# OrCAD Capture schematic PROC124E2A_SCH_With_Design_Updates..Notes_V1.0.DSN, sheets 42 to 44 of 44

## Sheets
42 41. OSCILLATOR: size C; title: OSCILLATOR
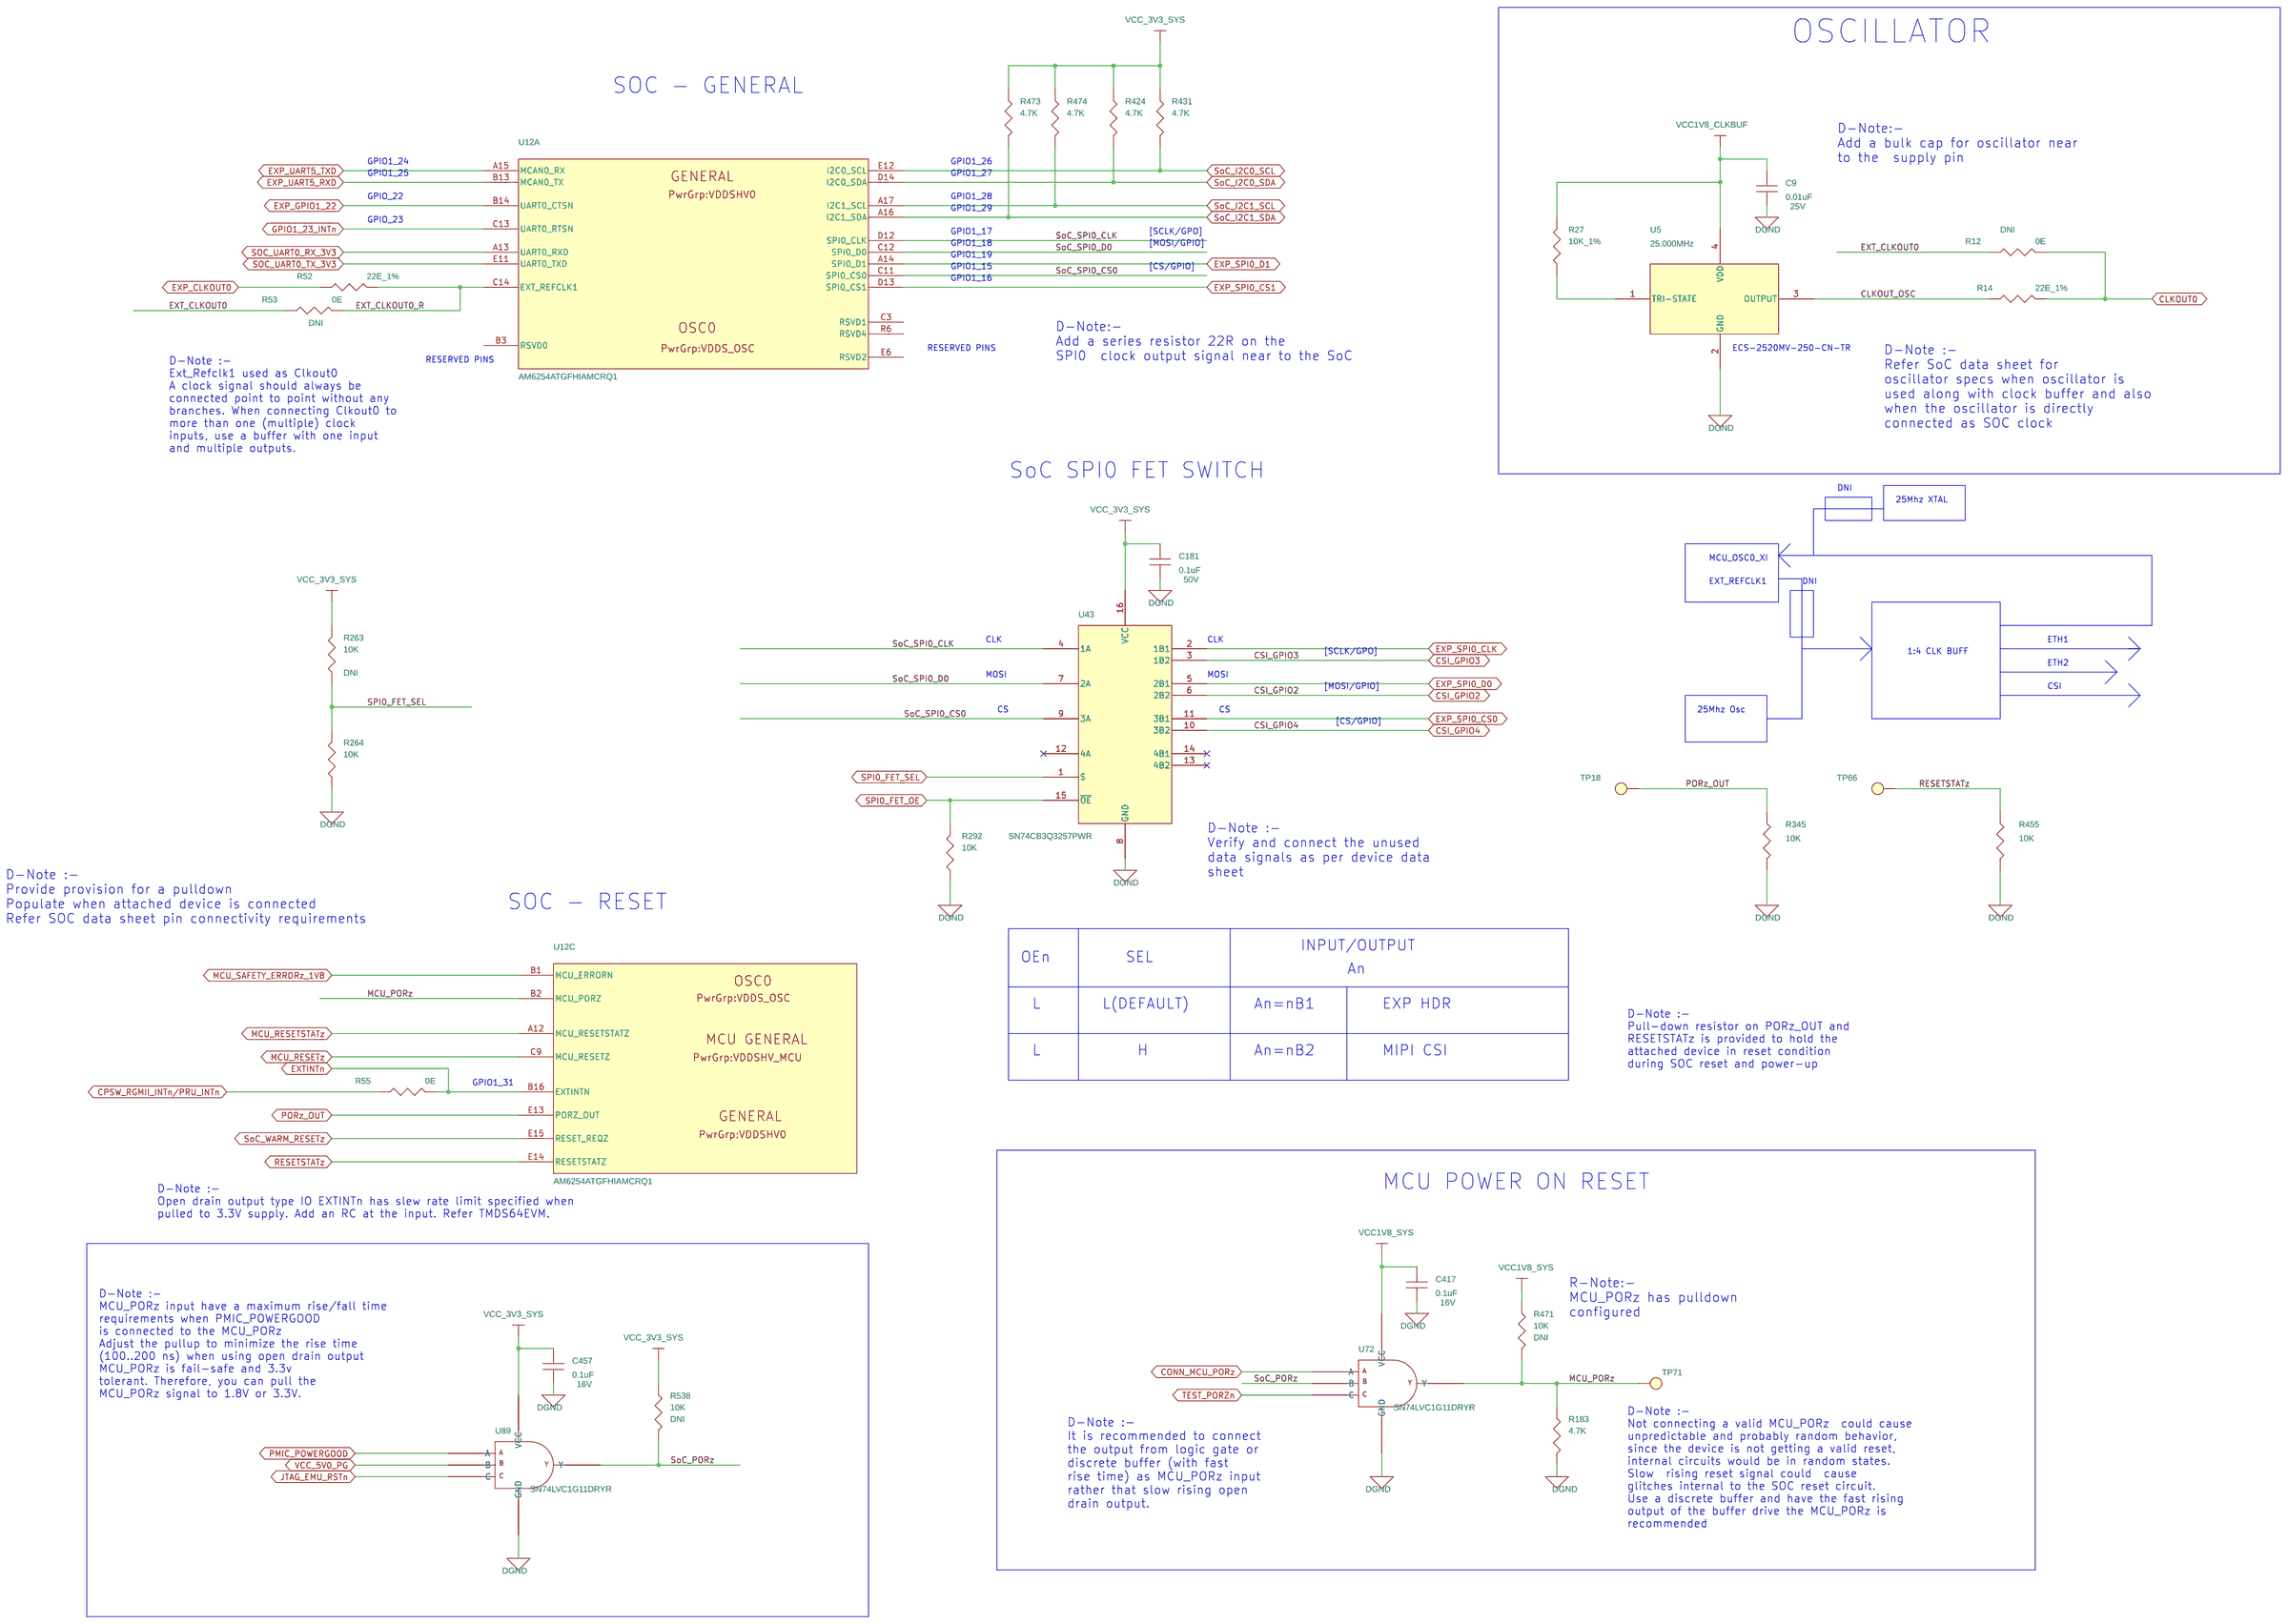
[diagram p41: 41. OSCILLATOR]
43 42. RESET: size C; title: RESET
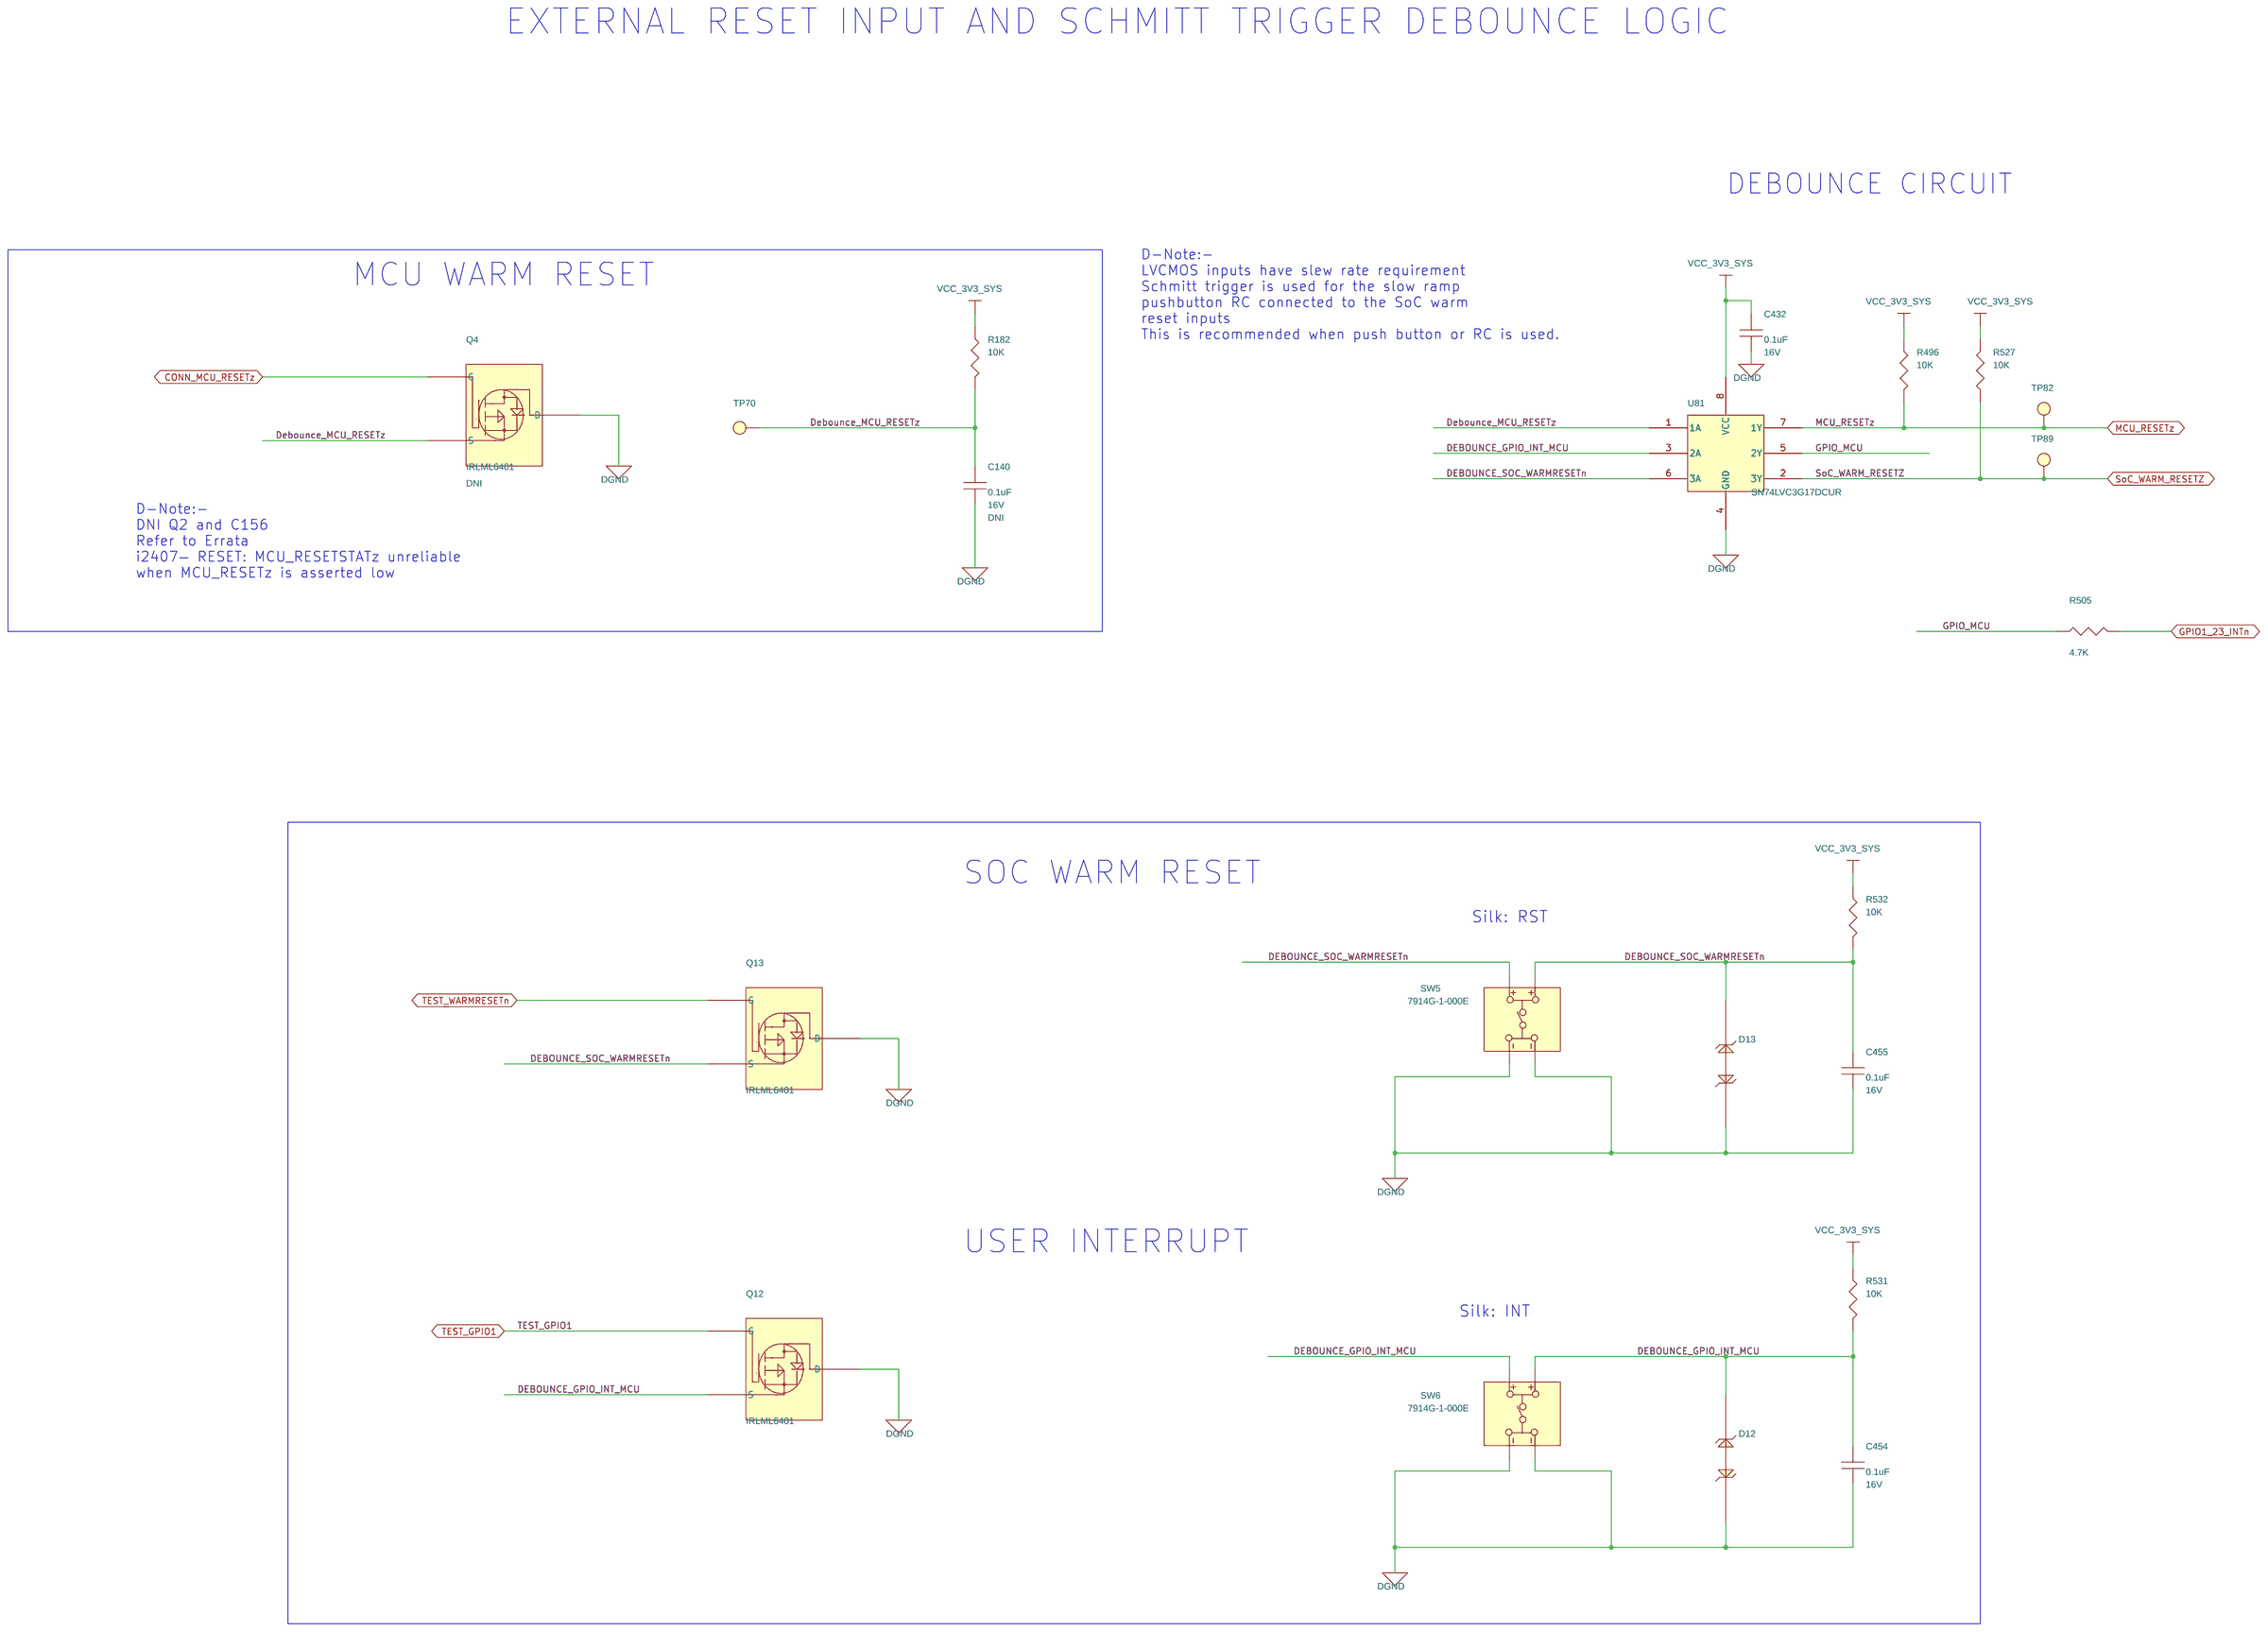
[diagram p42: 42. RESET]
44 44. ACCESSORIES: title: HARDWARE SCHEMATICS
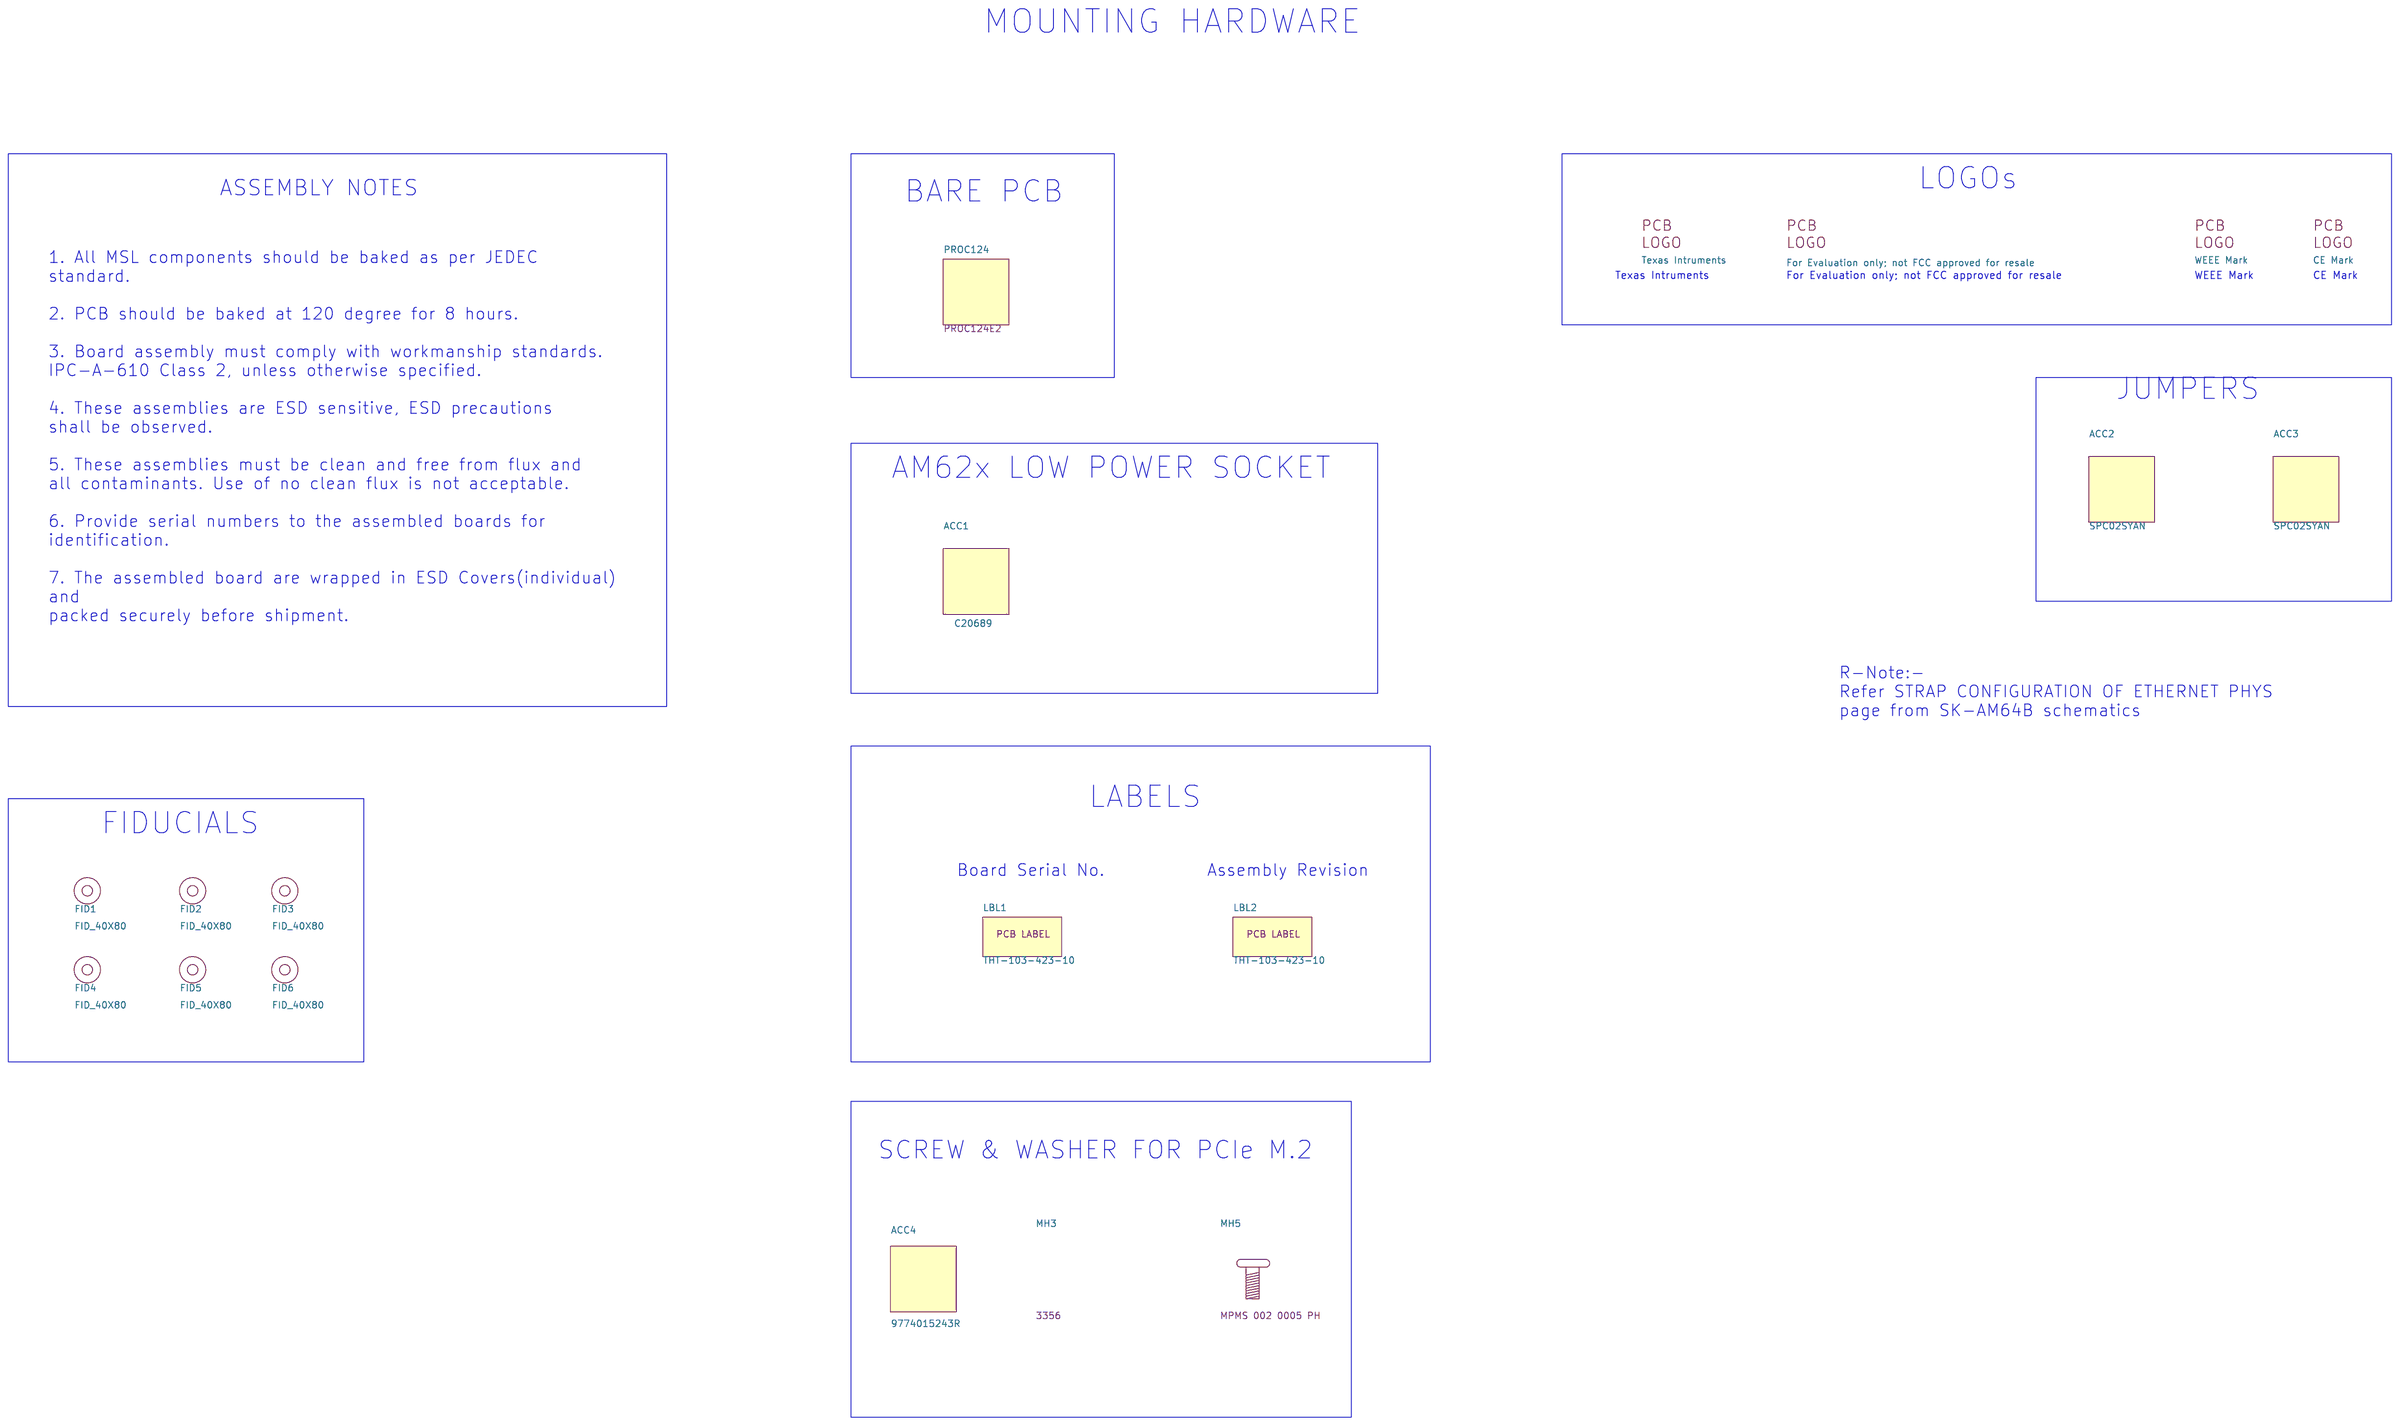
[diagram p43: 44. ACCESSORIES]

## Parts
sheet 15. SOC POWER CAPS
U12  AM6254ATGFHIAMCRQ1  [FCBGA441_31-49_680X680_2-6]  (sections A,B,C,D,E,F,G,H,I,J,K,L,M,N,O,P,Q,R)
sheet 41. OSCILLATOR
C9  0.01uF  [CAP0201_0-5]
C181  0.1uF  [CAP0402_0-75]
C417  0.1uF  [CAP0201_0-5]
C457  0.1uF  [CAP0201_0-5]
R12  0E  [RES0201_0-5]
R14  22E_1%  [RES0201_0-5]
R27  10K_1%  [RES0201_0-5]
R52  22E_1%  [RES0201_0-5]
R53  0E  [RES0201_0-5]
R55  0E  [RES0201_0-5]
R183  4.7K  [RES0201_0-5]
R263  10K  [RES0201_0-5]
R264  10K  [RES0201_0-5]
R292  10K  [RES0201_0-5]
R345  10K  [RES0201_0-5]
R424  4.7K  [RES0201_0-5]
R431  4.7K  [RES0201_0-5]
R455  10K  [RES0201_0-5]
R471  10K  [RES0201_0-5]
R473  4.7K  [RES0201_0-5]
R474  4.7K  [RES0201_0-5]
R538  10K  [RES0201_0-5]
TP18  TP20_SMD  [TP20_SMD]
TP66  TP20_SMD  [TP20_SMD]
TP71  TP20_SMD  [TP20_SMD]
U5  25.000MHz  [OSC4_ECS-2520MV_100X80_SMD_0-9]
U43  SN74CB3Q3257PWR  [TSSOP16_25-59_205X180]
U72  SN74LVC1G11DRYR  [SON6_SN74LVC2G17_40X60_0-6]
U89  SN74LVC1G11DRYR  [SON6_SN74LVC2G17_40X60_0-6]
sheet 42. RESET
C140  0.1uF  [CAP0201_0-5]
C432  0.1uF  [CAP0201_0-5]
C454  0.1uF  [CAP0201_0-5]
C455  0.1uF  [CAP0201_0-5]
D12  TPD1E10B06DPYR  [DIO_DFN0402_0-5]
D13  TPD1E10B06DPYR  [DIO_DFN0402_0-5]
Q4  IRLML6401  [TO_SOT23-123]
Q12  IRLML6401  [TO_SOT23-123]
Q13  IRLML6401  [TO_SOT23-123]
R182  10K  [RES0201_0-5]
R496  10K  [RES0201_0-5]
R505  4.7K  [RES0201_0-5]
R527  10K  [RES0201_0-5]
R531  10K  [RES0201_0-5]
R532  10K  [RES0201_0-5]
SW5  7914G-1-000E  [SW4_100X216_200X200_SMD_4-2]
SW6  7914G-1-000E  [SW4_100X216_200X200_SMD_4-2]
TP70  TP20_SMD  [TP20_SMD]
TP82  TP20_SMD  [TP20_SMD]
TP89  TP20_SMD  [TP20_SMD]
U81  SN74LVC3G17DCUR  [VSSOP8_19-68_85X95_0-9]
sheet 44. ACCESSORIES
ACC1  C20689  [BGASKT435_C20689_880X880_11]
ACC2  SPC02SYAN  [NA]
ACC3  SPC02SYAN  [NA]
ACC4  9774015243R  [NA]
FID1  FID_40X80  [FID_40X80]
FID2  FID_40X80  [FID_40X80]
FID3  FID_40X80  [FID_40X80]
FID4  FID_40X80  [FID_40X80]
FID5  FID_40X80  [FID_40X80]
FID6  FID_40X80  [FID_40X80]
LBL1  THT-103-423-10  [NA]
LBL2  THT-103-423-10  [NA]
LOGO1  Texas Intruments  [TI_Stacked_Overlay_Small]
LOGO2  For Evaluation only; not FCC approved for resale  [FCC_disclaimer]
LOGO3  WEEE Mark  [TI_Stacked_Overlay_Small]
LOGO4  CE Mark  [TI_Stacked_Overlay_Small]
MH3  FLAT WASHER_M2  [NA]
MH5  PAN HEAD_M2 X 5  [NA]
PCB1  PROC124

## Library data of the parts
U12 = AM6254ATGFHIAMCRQ1_FCBGA441: IC AM62Q SoC MICROPROCESSOR FCBGA441; Chkd/date: PRADEEP/180324; Crtd /date: TAMILARASU/180324; Custom_Duty: 15%; Customs_HS_Code: 85423100; Distributor_name: NA; Distributor_part_number: NA; Footprint Path: Y:\MIS_DATABASE\Library\ALTIUM_TOOL\PCB_FOOTPRINTS\Altium_Footprint_Lib.PcbLib; Height: 2.57MM; Library Path: Y:\MIS_DATABASE\Library\ALTIUM_TOOL\SCHEMATICS_PARTS\MS_MICROPROCESSOR_Library.schlib; Mfr_name: TEXAS INSTRUMENTS; Mistral Part No: 141224030001-R; Package: FCBGA441; Part_type: ICS\DIGITAL\MICROPROCESSOR; Project: TI_AM62Q_BRD; RoHS: NA; Temperature: NA; Tolerance: NA; Voltage: NA; Wattage: NA; Weight: NA; Datasheet: Y:\MIS_DATABASE\DATASHEETS\ICS\DIGITAL\MICROCONTROLLER\AM62Q-SoC.PDF
C9 = CAP: CAP CERAMIC 0.01uF 25V 10% X5R 0201; Chkd/date: MANIRAJA/230118; Crtd /date: MANIRAJA/230118; Custom_Duty: 15%; Customs_HS_Code: 85322990; Distributor_name: DIGIKEY; Distributor_part_number: GRM033R61E103KA12J-ND; Footprint Path: Y:\MIS_DATABASE\Library\ALTIUM_TOOL\PCB_FOOTPRINTS\Altium_Footprint_Lib.PcbLib; Height: 0.33MM; Library Path: Y:\MIS_DATABASE\Library\ALTIUM_TOOL\SCHEMATICS_PARTS\MS_DISCRETE_Library.schlib; Mfr_name: MURATA; Mfr_part_number: GRM033R61E103KA12J; Mistral Part No: 120018010007-R; Package: 0201; Part_type: CAPACITORS\CERAMIC; Project: TI_MAXIE_CPB; RoHS: RoHS; Temperature: -55°C+85°C; Tolerance: 10%; Voltage: 25V; Wattage: NA; Weight: 0.33mg; Datasheet: Y:\MIS_DATABASE\DATASHEETS\CAPACITORS\GRM033R61E103KA12.PDF
C181 = CAP: CAP CERAMIC 0.1uF 50V 10% X7R 0402; Alt_Mfr_name: YAGEO AMERICA; Alt_Mfr_part_number: CC0402KRX5R8BB104; Chkd/date: MANIRAJA/261020; Crtd /date: ALVY/211020; Custom_Duty: 15%; Customs_HS_Code: 85322990; Distributor_name: DIGIKEY; Distributor_part_number: 490-10700-1-ND; Footprint Path: Y:\MIS_DATABASE\Library\ALTIUM_TOOL\PCB_FOOTPRINTS\Altium_Footprint_Lib.PcbLib; Height: 0.55MM; Library Path: Y:\MIS_DATABASE\Library\ALTIUM_TOOL\SCHEMATICS_PARTS\MS_DISCRETE_Library.schlib; Mfr_name: MURATA; Mfr_part_number: GRM155R71H104KE14D; Mistral Part No: 120011100014-R; Package: 0402; Part_type: CAPACITORS\CERAMIC; Project: J7_CP; RoHS: RoHS; Temperature: -55°C+125°C; Tolerance: 10%; Voltage: 50V; Wattage: NA; Weight: 3.1mg; Datasheet: Y:\MIS_DATABASE\DATASHEETS\CAPACITORS\GRM155R71H104KE14.PDF
C417 C432 C454 C455 C457 = CAP: CAP CERAMIC 0.1uF 16V 10% X5R 0201; Alt_Mfr_name: YAGEO AMERICA; Alt_Mfr_part_number: CC0402KRX5R8BB104; Chkd/date: MANIRAJA/230118; Crtd /date: MANIRAJA/230118; Custom_Duty: 15%; Customs_HS_Code: 85322990; Distributor_name: DIGIKEY; Distributor_part_number: 490-14305-1-ND; Footprint Path: Y:\MIS_DATABASE\Library\ALTIUM_TOOL\PCB_FOOTPRINTS\Altium_Footprint_Lib.PcbLib; Height: 0.33MM; Library Path: Y:\MIS_DATABASE\Library\ALTIUM_TOOL\SCHEMATICS_PARTS\MS_DISCRETE_Library.schlib; Mfr_name: MURATA; Mfr_part_number: GRM033R61C104KE14D; Mistral Part No: 120009030072-R; Package: 0201; Part_type: CAPACITORS\CERAMIC; Project: TI_MAXIE_CPB; RoHS: RoHS; Temperature: -55°C+85°C; Tolerance: 10%; Voltage: 16V; Wattage: NA; Weight: 0.33mg; Datasheet: Y:\MIS_DATABASE\DATASHEETS\CAPACITORS\GRM033R61C104KE14.PDF
R12 R53 = RESISTOR: RES 0E 1/20W 5% 0201; Assembly_Instruction: DNI; Chkd/date: NAVEED/301214; Crtd /date: MUDDU/120710; Custom_Duty: 15%; Customs_HS_Code: 85332119; Distributor_name: DIGIKEY; Distributor_part_number: 311-0.0NCT-ND; Footprint Path: Y:\MIS_DATABASE\Library\ALTIUM_TOOL\PCB_FOOTPRINTS\Altium_Footprint_Lib.PcbLib; Height: 0.26MM; Library Path: Y:\MIS_DATABASE\Library\ALTIUM_TOOL\SCHEMATICS_PARTS\MS_DISCRETE_Library.schlib; Mfr_name: YAGEO AMERICA; Mfr_part_number: RC0201JR-070RL; Mistral Part No: 110010070067-R; Package: 0201; Part_type: RESISTORS\FIXED; Project: PB_BUGBASE; RoHS: RoHS; Temperature: -55°C+125°C; Tolerance: 5%; Voltage: NA; Wattage: 1/20W; Weight: 0.17mg; Datasheet: Y:\MIS_DATABASE\DATASHEETS\RESISTORS\RCXXXXL-SER_MAR18.PDF
R14 R52 = RESISTOR: RES 22E 1/20W 1% 0201; Chkd/date: PRAVEEN/080922; Crtd /date: TAMILARASU/080922; Custom_Duty: 15%; Customs_HS_Code: 85332119; Distributor_name: DIGIKEY; Distributor_part_number: P122843CT-ND; Footprint Path: Y:\MIS_DATABASE\Library\ALTIUM_TOOL\PCB_FOOTPRINTS\Altium_Footprint_Lib.PcbLib; Height: 0.26MM; Library Path: Y:\MIS_DATABASE\Library\ALTIUM_TOOL\SCHEMATICS_PARTS\MS_DISCRETE_Library.schlib; Mfr_name: PANASONIC-ECG; Mfr_part_number: ERJ-1GNF22R0C; Mistral Part No: 110022090007-R; Package: 0201; Part_type: RESISTORS\FIXED; Project: SK AM62Q LP EVM BRD; RoHS: RoHS; Temperature: -55°C+125°C; Tolerance: 1%; Voltage: NA; Wattage: 1/20W; Weight: 0.15mg; Datasheet: Y:\MIS_DATABASE\DATASHEETS\RESISTORS\PAN-ERJSER_NOV17.PDF
R27 = RESISTOR: RES 10K 1/20W 1% 0201; Chkd/date: VASANTHA/270117; Crtd /date: MANIRAJA/270117; Custom_Duty: 15%; Customs_HS_Code: 85332119; Distributor_name: DIGIKEY; Distributor_part_number: 311-10.0KMCT-ND; Footprint Path: Y:\MIS_DATABASE\Library\ALTIUM_TOOL\PCB_FOOTPRINTS\Altium_Footprint_Lib.PcbLib; Height: 0.26MM; Library Path: Y:\MIS_DATABASE\Library\ALTIUM_TOOL\SCHEMATICS_PARTS\MS_DISCRETE_Library.schlib; Mfr_name: YAGEO AMERICA; Mfr_part_number: RC0201FR-0710KL; Mistral Part No: 110011040018-R; Package: 0201; Part_type: RESISTORS\FIXED; Project: GOLDEN-I LITE; RoHS: RoHS; Temperature: -55°C+125°C; Tolerance: 1%; Voltage: NA; Wattage: 1/20W; Weight: 0.17mg; Datasheet: Y:\MIS_DATABASE\DATASHEETS\RESISTORS\RCXXXXL-SER_MAR18.PDF
R55 = RESISTOR: RES 0E 1/20W 5% 0201; Chkd/date: NAVEED/301214; Crtd /date: MUDDU/120710; Custom_Duty: 15%; Customs_HS_Code: 85332119; Distributor_name: DIGIKEY; Distributor_part_number: 311-0.0NCT-ND; Footprint Path: Y:\MIS_DATABASE\Library\ALTIUM_TOOL\PCB_FOOTPRINTS\Altium_Footprint_Lib.PcbLib; Height: 0.26MM; Library Path: Y:\MIS_DATABASE\Library\ALTIUM_TOOL\SCHEMATICS_PARTS\MS_DISCRETE_Library.schlib; Mfr_name: YAGEO AMERICA; Mfr_part_number: RC0201JR-070RL; Mistral Part No: 110010070067-R; Package: 0201; Part_type: RESISTORS\FIXED; Project: PB_BUGBASE; RoHS: RoHS; Temperature: -55°C+125°C; Tolerance: 5%; Voltage: NA; Wattage: 1/20W; Weight: 0.17mg; Datasheet: Y:\MIS_DATABASE\DATASHEETS\RESISTORS\RCXXXXL-SER_MAR18.PDF
R183 R424 R431 R473 R474 = RESISTOR: RES 4.7K 1/20W 5% 0201; Chkd/date: MANIRAJA/200921; Crtd /date: ALVY/200921; Custom_Duty: 15%; Customs_HS_Code: 85332119; Distributor_name: DIGIKEY; Distributor_part_number: 311-4.7KNCT-ND; Footprint Path: Y:\MIS_DATABASE\Library\ALTIUM_TOOL\PCB_FOOTPRINTS\Altium_Footprint_Lib.PcbLib; Height: 0.26MM; Library Path: Y:\MIS_DATABASE\Library\ALTIUM_TOOL\SCHEMATICS_PARTS\MS_DISCRETE_Library.schlib; Mfr_name: YAGEO AMERICA; Mfr_part_number: RC0201JR-074K7L; Mistral Part No: 110021090007-R; Package: 0201; Part_type: RESISTORS\FIXED; Project: TI_AM62x SKEVM_BRD; RoHS: RoHS; Temperature: -55°C+125°C; Tolerance: 5%; Voltage: NA; Wattage: 1/20W; Weight: 0.17mg; Datasheet: Y:\MIS_DATABASE\DATASHEETS\RESISTORS\RCXXXXL-SER_MAR18.PDF
R263 R471 R538 = RESISTOR: RES 10K 1/20W 5% 0201; Assembly_Instruction: DNI; Chkd/date: MANIRAJA/050517; Crtd /date: MANIRAJA/050517; Custom_Duty: 15%; Customs_HS_Code: 85332119; Distributor_name: DIGIKEY; Distributor_part_number: 311-10KNCT-ND; Footprint Path: Y:\MIS_DATABASE\Library\ALTIUM_TOOL\PCB_FOOTPRINTS\Altium_Footprint_Lib.PcbLib; Height: 0.26MM; Library Path: Y:\MIS_DATABASE\Library\ALTIUM_TOOL\SCHEMATICS_PARTS\MS_DISCRETE_Library.schlib; Mfr_name: YAGEO AMERICA; Mfr_part_number: RC0201JR-0710KL; Mistral Part No: 110010070051-R; Package: 0201; Part_type: RESISTORS\FIXED; Project: GOLDEN-I LITE; RoHS: RoHS; Temperature: -55°C+125°C; Tolerance: 5%; Voltage: NA; Wattage: 1/20W; Weight: 0.17mg; Datasheet: Y:\MIS_DATABASE\DATASHEETS\RESISTORS\RCXXXXL-SER_MAR18.PDF
R182 R264 R292 R345 R455 R496 R527 R531 R532 = RESISTOR: RES 10K 1/20W 5% 0201; Chkd/date: MANIRAJA/050517; Crtd /date: MANIRAJA/050517; Custom_Duty: 15%; Customs_HS_Code: 85332119; Distributor_name: DIGIKEY; Distributor_part_number: 311-10KNCT-ND; Footprint Path: Y:\MIS_DATABASE\Library\ALTIUM_TOOL\PCB_FOOTPRINTS\Altium_Footprint_Lib.PcbLib; Height: 0.26MM; Library Path: Y:\MIS_DATABASE\Library\ALTIUM_TOOL\SCHEMATICS_PARTS\MS_DISCRETE_Library.schlib; Mfr_name: YAGEO AMERICA; Mfr_part_number: RC0201JR-0710KL; Mistral Part No: 110010070051-R; Package: 0201; Part_type: RESISTORS\FIXED; Project: GOLDEN-I LITE; RoHS: RoHS; Temperature: -55°C+125°C; Tolerance: 5%; Voltage: NA; Wattage: 1/20W; Weight: 0.17mg; Datasheet: Y:\MIS_DATABASE\DATASHEETS\RESISTORS\RCXXXXL-SER_MAR18.PDF
TP18 TP66 TP70 TP71 TP82 TP89 = TESTPOINT: TESTPOINT CIR 20 SMD; Chkd/date: SHREESHAIL/171006; Crtd /date: MAZHAR/171006; Custom_Duty: NA; Customs_HS_Code: NA; Distributor_name: NA; Distributor_part_number: NA; Footprint Path: Y:\MIS_DATABASE\Library\ALTIUM_TOOL\PCB_FOOTPRINTS\Altium_Footprint_Lib.PcbLib; Height: NA; Library Path: Y:\MIS_DATABASE\Library\ALTIUM_TOOL\SCHEMATICS_PARTS\MS_DISCRETE_Library.schlib; MECHANICAL 3D STEP FILE: NA; Mfr_name: LOCAL; Mistral Part No: NA; Package: SMD; Project: BT MODULE_CSRBC04; RoHS: NA; Temperature: NA; Tolerance: NA; Voltage: NA; Wattage: NA; Weight: NA; Datasheet: NA
U5 = OSC4_ASFL3: OSC 25.000MHz CMOS SMD; Chkd/date: MANIRAJA/181120; Crtd /date: ALVY/181120; Custom_Duty: 24%; Customs_HS_Code: 85437099; Distributor_name: DIGIKEY; Distributor_part_number: XC2752CT-ND; Footprint Path: Y:\MIS_DATABASE\Library\ALTIUM_TOOL\PCB_FOOTPRINTS\Altium_Footprint_Lib.PcbLib; Height: 0.90MM; Library Path: Y:\MIS_DATABASE\Library\ALTIUM_TOOL\SCHEMATICS_PARTS\MS_DISCRETE_Library.schlib; Mfr_name: ECS INC; Mfr_part_number: ECS-2520MV-250-CN-TR; Mistral Part No: 130020110041-R; Package: SMD; Part_type: OSCILLATORS; Project: AM64X_SKEVM; RoHS: RoHS; Temperature: -40°C+85°C; Tolerance: NA; Voltage: NA; Wattage: NA; Weight: 311mg; Datasheet: Y:\MIS_DATABASE\DATASHEETS\MISC\CRY_OSC\ECS-2520MV.PDF
U43 = SN74CB3Q3257PWR_TSSOP16: IC 4BIT 1-OF-2 FET MULTIPLEXER/DEMULTIPLEXER TSSOP16; Chkd/date: SUHAS/251010; Crtd /date: USMAN/060109; Custom_Duty: 15%; Customs_HS_Code: 85423100; Distributor_name: DIGIKEY; Distributor_part_number: 296-19138-1-ND; Footprint Path: Y:\MIS_DATABASE\Library\ALTIUM_TOOL\PCB_FOOTPRINTS\Altium_Footprint_Lib.PcbLib; Footprint Ref: TSSOP16_25-59_205X180_1-2; Height: 1.20MM; Library Path: Y:\MIS_DATABASE\Library\ALTIUM_TOOL\SCHEMATICS_PARTS\MS_COMBINATIONAL_Library.schlib; MECHANICAL 3D STEP FILE: TSSOP16_25-59_205X180_1-2; Mfr_name: TEXAS INSTRUMENTS; Mistral Part No: 141009030117-R; Package: TSSOP16; Part_type: ICS\DIGITAL\COMBINATIONAL; Project: OMAP_EVM; RoHS: Sb/ Br FREE; Temperature: -40°C+85°C; Datasheet: Y:\MIS_DATABASE\DATASHEETS\ICS\DIGITAL\COMBINATIONAL\SN74CB3Q3257.PDF
U72 U89 = SN74LVC1G11DCKR_SC70-6: IC SINGLE 3-INPUT POSITIVE-AND GATE SON6; Chkd/date: MANIRAJA/270121; Crtd /date: ALVY/270121; Custom_Duty: 15%; Customs_HS_Code: 85423100; Distributor_name: DIGIKEY; Distributor_part_number: 296-30120-1-ND; Footprint Path: Y:\MIS_DATABASE\Library\ALTIUM_TOOL\PCB_FOOTPRINTS\Altium_Footprint_Lib.PcbLib; Height: 0.60MM; Library Path: Y:\MIS_DATABASE\Library\ALTIUM_TOOL\SCHEMATICS_PARTS\MS_GATE_Library.schlib; Mfr_name: TEXAS INSTRUMENTS; Mistral Part No: 141021010013-R; Package: SON6; Part_type: ICS\DIGITAL\GATES; Project: AM64X_SKEVM; RoHS: RoHS; Temperature: -40°C+125°C; Tolerance: NA; Voltage: NA; Wattage: NA; Weight: 33mg; Datasheet: Y:\MIS_DATABASE\DATASHEETS\ICS\DIGITAL\GATES\SN74LVC1G_NOV16.PDF
C140 = CAP: CAP CERAMIC 0.1uF 16V 10% X5R 0201; Alt_Mfr_name: YAGEO AMERICA; Alt_Mfr_part_number: CC0402KRX5R8BB104; Assembly_Instruction: DNI; Chkd/date: MANIRAJA/230118; Crtd /date: MANIRAJA/230118; Custom_Duty: 15%; Customs_HS_Code: 85322990; Distributor_name: DIGIKEY; Distributor_part_number: 490-14305-1-ND; Footprint Path: Y:\MIS_DATABASE\Library\ALTIUM_TOOL\PCB_FOOTPRINTS\Altium_Footprint_Lib.PcbLib; Height: 0.33MM; Library Path: Y:\MIS_DATABASE\Library\ALTIUM_TOOL\SCHEMATICS_PARTS\MS_DISCRETE_Library.schlib; Mfr_name: MURATA; Mfr_part_number: GRM033R61C104KE14D; Mistral Part No: 120009030072-R; Package: 0201; Part_type: CAPACITORS\CERAMIC; Project: TI_MAXIE_CPB; RoHS: RoHS; Temperature: -55°C+85°C; Tolerance: 10%; Voltage: 16V; Wattage: NA; Weight: 0.33mg; Datasheet: Y:\MIS_DATABASE\DATASHEETS\CAPACITORS\GRM033R61C104KE14.PDF
D12 D13 = DIODE_SOD323: DIODE 1CH ESD PROTECTION X1SON2; Chkd/date: MANIRAJA/040420; Crtd /date: VASANTHA/181114; Custom_Duty: 15%; Customs_HS_Code: 85423100; Distributor_name: DIGIKEY; Distributor_part_number: 296-30406-1-ND; Footprint Path: Y:\MIS_DATABASE\Library\ALTIUM_TOOL\PCB_FOOTPRINTS\Altium_Footprint_Lib.PcbLib; Height: 0.45MM; Library Path: Y:\MIS_DATABASE\Library\ALTIUM_TOOL\SCHEMATICS_PARTS\MS_DISCRETE_Library.schlib; Mfr_name: TEXAS INSTRUMENTS; Mistral Part No: 130014110022-R; Package: X1SON2; Part_type: DIODE; Project: GALILEO_EVM; RoHS: RoHS; Temperature: -40°C+125°C; Tolerance: NA; Voltage: NA; Wattage: NA; Weight: 1mg; Datasheet: Y:\MIS_DATABASE\DATASHEETS\ICS\INTERFACE\TPD1E10B06-SER.PDF
Q4 = MOSFET_IRLML6401TR: TRANSISTOR MOSFET P-CHANNEL SOT23-3; Assembly_Instruction: DNI; Chkd/date: SHREESHAIL/020206; Crtd /date: MAZHAR/040505; Custom_Duty: 15%; Customs_HS_Code: 85412900; Distributor_name: DIGIKEY; Distributor_part_number: IRLML6401PBFCT-ND; Height: 1.11MM; Mfr_name: IRF; Mfr_part_number: IRLML6401TRPBF; Mistral Part No: 130009031213-P; Package: SOT23-3; Part_type: TRANSISTOR\MOSFET; Project: G4_SVGA; RoHS: Pb-Free; Temperature: -55°C+150°C; Tolerance: NA; Voltage: NA; Wattage: NA; Weight: NA; Datasheet: Y:\MIS_DATABASE\DATASHEETS\DISCRETES\TRANSISTORS_FETS\IRLML6401.PDF
Q12 Q13 = MOSFET_IRLML6401TR: TRANSISTOR MOSFET P-CHANNEL SOT23-3; Chkd/date: SHREESHAIL/020206; Crtd /date: MAZHAR/040505; Custom_Duty: 15%; Customs_HS_Code: 85412900; Distributor_name: DIGIKEY; Distributor_part_number: IRLML6401PBFCT-ND; Height: 1.11MM; Mfr_name: IRF; Mfr_part_number: IRLML6401TRPBF; Mistral Part No: 130009031213-P; Package: SOT23-3; Part_type: TRANSISTOR\MOSFET; Project: G4_SVGA; RoHS: Pb-Free; Temperature: -55°C+150°C; Tolerance: NA; Voltage: NA; Wattage: NA; Weight: NA; Datasheet: Y:\MIS_DATABASE\DATASHEETS\DISCRETES\TRANSISTORS_FETS\IRLML6401.PDF
R505 = RESISTOR: RES 4.7K 1/20W 5% 0201; Chkd/date: MANIRAJA/200921; Crtd /date: ALVY/200921; Custom_Duty: 15%; Customs_HS_Code: 85332119; Distributor_name: DIGIKEY; Distributor_part_number: 311-4.7KNCT-ND; Footprint Path: Y:\MIS_DATABASE\Library\ALTIUM_TOOL\PCB_FOOTPRINTS\Altium_Footprint_Lib.PcbLib; Height: 0.26MM; Library Path: Y:\MIS_DATABASE\Library\ALTIUM_TOOL\SCHEMATICS_PARTS\MS_DISCRETE_Library.schlib; Manufacturer: YAGEO AMERICA; Mfr_name: YAGEO AMERICA; Mfr_part_number: RC0201JR-074K7L; Mistral Part No: 110021090007-R; Package: 0201; Part_type: RESISTORS\FIXED; Project: TI_AM62x SKEVM_BRD; RoHS: RoHS; Temperature: -55°C+125°C; Tolerance: 5%; Voltage: NA; Wattage: 1/20W; Weight: 0.17mg; Datasheet: Y:\MIS_DATABASE\DATASHEETS\RESISTORS\RCXXXXL-SER_MAR18.PDF
SW5 SW6 = 7914G-1-000E__7914G: SWITCH SPST-NO 4MM SQ SMD 7914G; Chkd/date: VASANTHA/271216; Crtd /date: BAVISH/051010; Custom_Duty: 24%; Customs_HS_Code: 85369090; Distributor_name: DIGIKEY; Distributor_part_number: 7914G-000ECT-ND; Height: 4.19MM; Library Ref: 7914G-1-000E _7914G; Mfr_name: BOURNS; Mistral Part No: 130015110004-R; Package: 7914G; Part_type: ELECTRO-MECHANICAL\SWITCH; Project: AAAUC; RoHS: RoHS; Temperature: -55°C+125°C; Tolerance: NA; Voltage: NA; Wattage: NA; Weight: NA; Datasheet: Y:\MIS_DATABASE\DATASHEETS\ICS\DIGITAL\COMBINATIONAL\7914G-1-000E.PDF
U81 = SN74LVC3G17DCUR_VSSOP8: IC TRIPLE SCHMITT-TRIGGER BUFFER VSSOP8; Chkd/date: MANIRAJA/280917; Crtd /date: MANIRAJA/280917; Custom_Duty: 15%; Customs_HS_Code: 85423100; Distributor_name: DIGIKEY; Distributor_part_number: 296-18818-1-ND; Height: 0.90MM; Mfr_name: TEXAS INSTRUMENTS; Mistral Part No: 141017090019-R; Package: VSSOP8; Part_type: ICS\DIGITAL\COMBINATIONAL; Project: TI_MAXIE_CPB; RoHS: RoHS; Temperature: -40°C+125°C; Tolerance: NA; Voltage: NA; Wattage: NA; Weight: 9.6mg; Datasheet: Y:\MIS_DATABASE\DATASHEETS\ICS\DIGITAL\COMBINATIONAL\SN74LVC3G17.PDF
ACC1 = ACCESSORY: ACCESSORIE BGA SOCKET J7VCL MICROPROCESSOR BGA435; Chkd/date: ALVY/161220; Crtd /date: MANIRAJA/161220; Custom_Duty: NA; Customs_HS_Code: NA; Distributor_name: NA; Distributor_part_number: NA; Footprint Path: NA; Height: 10.93MM; Library Path: NA; Mfr_name: IRONWOOD ELECTRONICS; Mistral Part No: 160020120073; Package: BGA435; Part_type: ACCESSORIES; Project: J7VCL_EVM; RoHS: NA; Temperature: -55°C+160°C; Tolerance: NA; Voltage: NA; Wattage: NA; Weight: 19620mg; Datasheet: Y:\MIS_DATABASE\DATASHEETS\MISC\ACCESSORIES\C20689.PDF
ACC2 ACC3 = ACCESSORY: ACCESSORIE JUMPER SHORTING GOLD FLASH; Chkd/date: SUHAS\211010; Crtd /date: USMAN/301208; Distributor_name: DIGIKEY; Distributor_part_number: S9001-ND; Footprint Path: Y:\MIS_DATABASE\Library\ALTIUM_TOOL\PCB_FOOTPRINTS\Altium_Footprint_Lib.PcbLib; Library Path: Y:\MIS_DATABASE\Library\ALTIUM_TOOL\SCHEMATICS_PARTS\MS_MECHANICAL_Library.schlib; Mfr_name: SULLINS CONNECTOR; Mistral Part No: 160009030153-R; Part_type: ACCESSORIES; Project: SMART VIEW_NVR; RoHS: RoHS; Temperature: -55°C+105°C; Datasheet: Y:\MIS_DATABASE\DATASHEETS\MISC\MODULES\SPC02SYAN.PDF
ACC4 = ACCESSORY: STANDOFF BOARD TO BOARD 1.50MM LENGTH FEMALE M2 THREADED SS; Chkd/date: MANIRAJA/280219; Crtd /date: ALVY/280219; Distributor_name: DIGIKEY; Distributor_part_number: 732-7069-1-ND; Mfr_name: WURTH ELECTRONICS; Mistral Part No: 160019020049-R; Package: SS; Part_type: MECHANICAL\STANDOFF; Project: TI_J7ES_EVM_CP; RoHS: RoHS; Weight: 178mg; Datasheet: Y:\MIS_DATABASE\DATASHEETS\MISC\MECHANICAL\9774015243R.PDF
FID1-FID6 = Fiducial
LBL1 LBL2 = ACCESSORY_THT-3-423-10: ACCESSORIE 1 WORKHORSE POLYSTER LABLE 0.25" X 1"; Chkd/date: MANIRAJA/270218; Crtd /date: ALVY/260218; Footprint Path: Y:\MIS_DATABASE\Library\ALTIUM_TOOL\PCB_FOOTPRINTS\Altium_Footprint_Lib.PcbLib; Library Path: Y:\MIS_DATABASE\Library\ALTIUM_TOOL\SCHEMATICS_PARTS\MS_MECHANICAL_Library.schlib; Mfr_name: BRADY; Mistral Part No: 160018020185; Part_type: ACCESSORIES; Project: TI_MAXIE_CPB
LOGO1 LOGO3 LOGO4 = TI_Logo
LOGO2 = FCC_disclaimer
MH3 = WASHER_FLAT: FLAT WASHER FOR M2 NYLON; Chkd/date: MANIRAJA/110319; Crtd /date: ALVY/110319; Distributor_name: DIGIKEY; Distributor_part_number: 36-3356-ND; Mfr_name: KEYSTONE; Mfr_part_number: 3356; Mistral Part No: 160019030017-R; Package: NYLON; Part_type: MECHANICAL\WASHERS; Project: TI_J7ES_EVM_CP; RoHS: RoHS; Datasheet: Y:\MIS_DATABASE\DATASHEETS\MISC\MECHANICAL\3356.PDF
MH5 = SCREW_PAN: PHILLIPS PAN HEAD SCREW - M2 X 5; Chkd/date: MANIRAJA/150319; Crtd /date: MANIRAJA/150319; Distributor_name: DIGIKEY; Distributor_part_number: H738-ND; Height: 5.00MM; Mfr_name: B AND F FASTENER; Mfr_part_number: MPMS 002 0005 PH; Mistral Part No: 160019030026-R; Part_type: MECHANICAL\SCREWS; Project: TI_J7ES_EVM_CP; RoHS: RoHS; Datasheet: Y:\MIS_DATABASE\DATASHEETS\MISC\MECHANICAL\SCREW_MPMSXXX.PDF
PCB1 = PCB_0: AM62x LOW POWER SKEVM; Mfr_part_number: PROC124E2

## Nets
DGND: C9.1 C140.1 C181.1 C417.1 C432.1 C454.1 C455.1 C457.1 D12.1 D13.1 Q4.3(D) Q12.3(D) Q13.3(D) R183.2 R264.1 R292.1 R345.2 R455.2 SW5.1 SW5.4 SW6.1 SW6.4 U5.2(GND) U43.8(GND) U72.2(GND) U81.4(GND) U89.2(GND) ; also on sheet 1 2 3 4 13 14 15 16 17 18 19 20 21 22 23 24 25 26 27 28 29 30 31 32 33 34 35 36 37 38 39 40 41
VCC1V8_CLKBUF: C9.2 R27.2 U5.4(VDD) ; also on sheet 25
VCC1V8_SYS: C417.2 R471.1 U72.5(VCC) ; also on sheet 4 16 19 20 22 25 34 37 39 40
VCC_3V3_SYS: C181.2 C432.2 C457.2 R182.1 R263.2 R424.1 R431.1 R473.1 R474.1 R496.1 R527.2 R531.1 R532.1 R538.1 U43.16(VCC) U81.8(VCC) U89.5(VCC) ; also on sheet 1 4 15 16 19 20 21 23 24 26 27 29 30 31 32 33 34 36 37 38 39 40 41
VCC_5V0_PG: U89.3(B) ; also on sheet 14
CLKOUT0: R12.2 R14.2 ; also on sheet 25
CLKOUT_OSC: R14.1 U5.3(OUTPUT)
CONN_MCU_PORz: U72.1(A) ; also on sheet 34
CONN_MCU_RESETz: Q4.1(G) ; also on sheet 34
CPSW_RGMII_INTn/PRU_INTn: R55.1 ; also on sheet 24 32
CSI_GPIO2: U43.6(2B2) ; also on sheet 38
CSI_GPIO3: U43.3(1B2) ; also on sheet 38
CSI_GPIO4: U43.10(3B2) ; also on sheet 38
DEBOUNCE_GPIO_INT_MCU: C454.2 D12.2 Q12.2(S) R531.2 SW6.2 SW6.3 U81.3(2A)
Debounce_MCU_RESETz: C140.2 Q4.2(S) R182.2 TP70.1(TP) U81.1(1A)
DEBOUNCE_SOC_WARMRESETn: C455.2 D13.2 Q13.2(S) R532.2 SW5.2 SW5.3 U81.6(3A)
EXP_CLKOUT0: R52.1 ; also on sheet 33
EXP_GPIO1_22: U12.B14(UART0_CTSN) ; also on sheet 33
EXP_SPI0_CLK: U43.2(1B1) ; also on sheet 33
EXP_SPI0_CS0: U43.11(3B1) ; also on sheet 33
EXP_SPI0_CS1: U12.D13(SPI0_CS1) ; also on sheet 33
EXP_SPI0_D0: U43.5(2B1) ; also on sheet 33
EXP_SPI0_D1: U12.A14(SPI0_D1) ; also on sheet 33
EXP_UART5_RXD: U12.B13(MCAN0_TX) ; also on sheet 33
EXP_UART5_TXD: U12.A15(MCAN0_RX) ; also on sheet 33
EXT_CLKOUT0: R12.1 R53.1
EXT_CLKOUT0_R: R52.2 R53.2 U12.C14(EXT_REFCLK1)
EXTINTn: R55.2 U12.B16(EXTINTN) ; also on sheet 4
GPIO1_23_INTn: R505.2 U12.C13(UART0_RTSN) ; also on sheet 39
GPIO_MCU: R505.1 U81.5(2Y)
JTAG_EMU_RSTn: U89.6(C) ; also on sheet 30
MCU_PORz: R183.1 R471.2 TP71.1(TP) U12.B2(MCU_PORZ) U72.4(Y)
MCU_RESETSTATz: U12.A12(MCU_RESETSTATZ) ; also on sheet 32 34
MCU_RESETz: R496.2 TP82.1(TP) U12.C9(MCU_RESETZ) U81.7(1Y)
MCU_SAFETY_ERRORz_1V8: U12.B1(MCU_ERRORN) ; also on sheet 34
PMIC_POWERGOOD: U89.1(A) ; also on sheet 4
PORz_OUT: R345.1 TP18.1(TP) U12.E13(PORZ_OUT) ; also on sheet 1 21 24 27
RESETSTATz: R455.1 TP66.1(TP) U12.E14(RESETSTATZ) ; also on sheet 1 4 20 21 22 24 27 32 37 38 39 40 41
SoC_I2C0_SCL: R431.2 U12.E12(I2C0_SCL) ; also on sheet 4 13 23 32 33 37
SoC_I2C0_SDA: R424.2 U12.D14(I2C0_SDA) ; also on sheet 4 13 23 32 33 37
SOC_I2C1_SCL: R474.2 U12.A17(I2C1_SCL) ; also on sheet 16 23 26 39 40 41
SOC_I2C1_SDA: R473.2 U12.A16(I2C1_SDA) ; also on sheet 16 23 26 39 40 41
SoC_PORz: R538.2 U72.3(B) U89.4(Y)
SoC_SPI0_CLK: U12.D12(SPI0_CLK) U43.4(1A)
SoC_SPI0_CS0: U12.C11(SPI0_CS0) U43.9(3A)
SoC_SPI0_D0: U12.C12(SPI0_D0) U43.7(2A)
SOC_UART0_RX_3V3: U12.A13(UART0_RXD) ; also on sheet 31
SOC_UART0_TX_3V3: U12.E11(UART0_TXD) ; also on sheet 31
SoC_WARM_RESETZ: R527.1 TP89.1(TP) U12.E15(RESET_REQZ) U81.2(3Y)
SPI0_FET_OE: R292.2 U43.15(~{OE}) ; also on sheet 39
SPI0_FET_SEL: R263.1 R264.2 U43.1(S) ; also on sheet 39
TEST_GPIO1: Q12.1(G) ; also on sheet 26 28
TEST_PORZn: U72.6(C) ; also on sheet 26 28
TEST_WARMRESETn: Q13.1(G) ; also on sheet 26 28
N16947096: R27.1 U5.1(TRI-STATE)

Not connected (* = marked no-connect by the designer): U12 B3(RSVD0) C3(RSVD1) E6(RSVD2) R6(RSVD4); U43 12(4A)* 13(4B2)* 14(4B1)*

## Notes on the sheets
sheet 42
- OSCILLATOR
- SOC - GENERAL
- D-Note:-
  Add a bulk cap for oscillator near
  to the  supply pin
- GPIO1_24
- GPIO1_26
- GPIO1_25
- GPIO1_27
- GPIO_22
- GPIO1_28
- GPIO1_29
- GPIO_23
- GPIO1_17
- [SCLK/GPO]
- GPIO1_18
- [MOSI/GPIO]
- GPIO1_19
- GPIO1_15
- [CS/GPIO]
- GPIO1_16
- D-Note:-
  Add a series resistor 22R on the
  SPI0  clock output signal near to the SoC
- D-Note :-
  Ext_Refclk1 used as Clkout0
  A clock signal should always be
  connected point to point without any
  branches. When connecting Clkout0 to
  more than one (multiple) clock
  inputs, use a buffer with one input
  and multiple outputs.
- RESERVED PINS
- RESERVED PINS
- ECS-2520MV-250-CN-TR
- D-Note :-
  Refer SoC data sheet for
  oscillator specs when oscillator is
  used along with clock buffer and also
  when the oscillator is directly
  connected as SOC clock
- SoC SPI0 FET SWITCH
- DNI
- 25Mhz XTAL
- MCU_OSC0_XI
- EXT_REFCLK1
- DNI
- CLK
- CLK
- ETH1
- [SCLK/GPO]
- 1:4 CLK BUFF
- ETH2
- MOSI
- MOSI
- [MOSI/GPIO]
- CSI
- CS
- CS
- 25Mhz Osc
- [CS/GPIO]
- D-Note :-
  Verify and connect the unused
  data signals as per device data
  sheet
- D-Note :-
  Provide provision for a pulldown
  Populate when attached device is connected
  Refer SOC data sheet pin connectivity requirements
- SOC - RESET
- INPUT/OUTPUT
- OEn
- SEL
- An
- L
- L(DEFAULT)
- An=nB1
- EXP HDR
- D-Note :-
  Pull-down resistor on PORz_OUT and
  RESETSTATz is provided to hold the
  attached device in reset condition
  during SOC reset and power-up
- L
- H
- An=nB2
- MIPI CSI
- GPIO1_31
- MCU POWER ON RESET
- D-Note :-
  Open drain output type IO EXTINTn has slew rate limit specified when
  pulled to 3.3V supply. Add an RC at the input. Refer TMDS64EVM.
- R-Note:-
  MCU_PORz has pulldown
  configured
- D-Note :-
  MCU_PORz input have a maximum rise/fall time
  requirements when PMIC_POWERGOOD
  is connected to the MCU_PORz
  Adjust the pullup to minimize the rise time
  (100..200 ns) when using open drain output
  MCU_PORz is fail-safe and 3.3v
  tolerant. Therefore, you can pull the
  MCU_PORz signal to 1.8V or 3.3V.
- D-Note :-
  Not connecting a valid MCU_PORz  could cause
  unpredictable and probably random behavior,
  since the device is not getting a valid reset,
  internal circuits would be in random states.
  Slow  rising reset signal could  cause
  glitches internal to the SOC reset circuit.
  Use a discrete buffer and have the fast rising
  output of the buffer drive the MCU_PORz is
  recommended
- D-Note :-
  It is recommended to connect
  the output from logic gate or
  discrete buffer (with fast
  rise time) as MCU_PORz input
  rather that slow rising open
  drain output.
sheet 43
- EXTERNAL RESET INPUT AND SCHMITT TRIGGER DEBOUNCE LOGIC
- DEBOUNCE CIRCUIT
- D-Note:-
  LVCMOS inputs have slew rate requirement
  Schmitt trigger is used for the slow ramp
  pushbutton RC connected to the SoC warm
  reset inputs
  This is recommended when push button or RC is used.
- MCU WARM RESET
- D-Note:-
  DNI Q2 and C156
  Refer to Errata
  i2407— RESET: MCU_RESETSTATz unreliable
  when MCU_RESETz is asserted low
- SOC WARM RESET
- Silk: RST
- USER INTERRUPT
- Silk: INT
sheet 44
- MOUNTING HARDWARE
- LOGOs
- ASSEMBLY NOTES
- BARE PCB
- 1. All MSL components should be baked as per JEDEC
  standard.
  2. PCB should be baked at 120 degree for 8 hours.
  3. Board assembly must comply with workmanship standards.
  IPC-A-610 Class 2, unless otherwise specified.
  4. These assemblies are ESD sensitive, ESD precautions
  shall be observed.
  5. These assemblies must be clean and free from flux and
  all contaminants. Use of no clean flux is not acceptable.
  6. Provide serial numbers to the assembled boards for
  identification.
  7. The assembled board are wrapped in ESD Covers(individual)
  and
  packed securely before shipment.
- Texas Intruments
- For Evaluation only; not FCC approved for resale
- WEEE Mark
- CE Mark
- JUMPERS
- AM62x LOW POWER SOCKET
- R-Note:-
  Refer STRAP CONFIGURATION OF ETHERNET PHYS
  page from SK-AM64B schematics
- LABELS
- FIDUCIALS
- Board Serial No.
- Assembly Revision
- SCREW & WASHER FOR PCIe M.2
